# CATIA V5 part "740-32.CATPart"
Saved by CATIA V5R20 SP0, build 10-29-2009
Part number: 740-32
Bounding box of the stored display mesh (mm): x -27.9 to 27.9, y -26 to 27.9, z -30 to 12
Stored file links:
  C:\Users\Utente\Desktop\IO LAVORO\3D X SITO CF\X SITO\740\740-32.CATPart
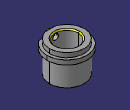
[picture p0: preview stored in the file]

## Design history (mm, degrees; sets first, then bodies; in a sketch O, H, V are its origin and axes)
Set1
  DatumSurface1 to DatumSurface35 "740-32"
Body1 (main body)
